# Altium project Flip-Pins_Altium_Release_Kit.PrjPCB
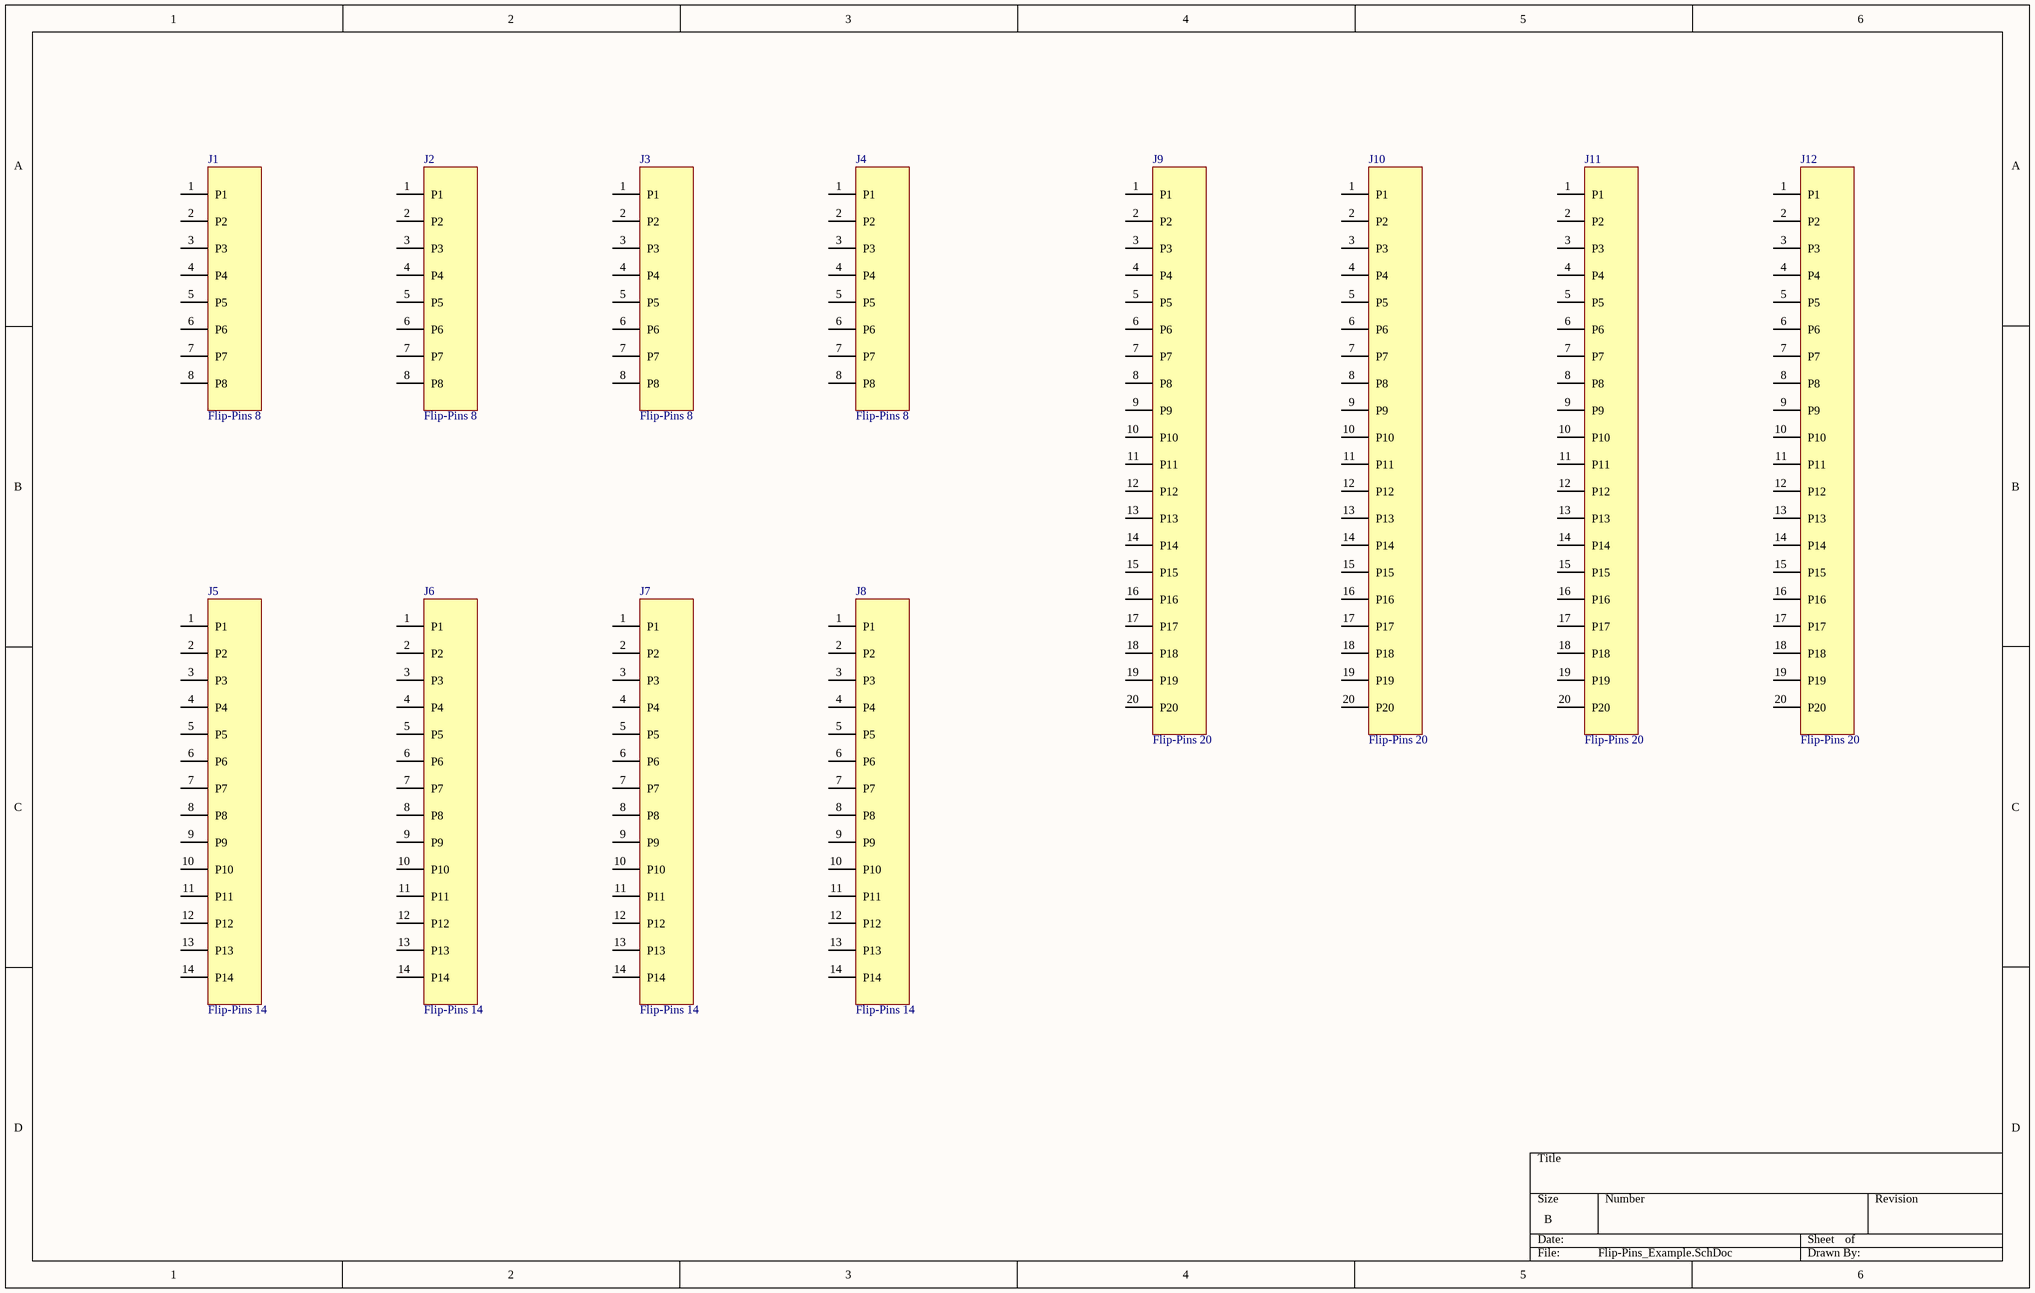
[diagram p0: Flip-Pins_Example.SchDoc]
1 sheet, 12 parts. Net scope: global (net labels, ports and power ports of the same name join across sheets).
Board file: Flip-Pins_Example.PcbDoc

## Sheet Flip-Pins_Example.SchDoc
size B

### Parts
J1  Flip-Pins 8  [Flip-Pins-08]
J2  Flip-Pins 8  [Flip-Pins-08]
J3  Flip-Pins 8  [Flip-Pins-08_Aligner]
J4  Flip-Pins 8  [Flip-Pins-08_Aligner]
J5  Flip-Pins 14  [Flip-Pins-14]
J6  Flip-Pins 14  [Flip-Pins-14]
J7  Flip-Pins 14  [Flip-Pins-14_Aligner]
J8  Flip-Pins 14  [Flip-Pins-14_Aligner]
J9  Flip-Pins 20  [Flip-Pins-20]
J10  Flip-Pins 20  [Flip-Pins-20]
J11  Flip-Pins 20  [Flip-Pins-20_Aligner]
J12  Flip-Pins 20  [Flip-Pins-20_Aligner]

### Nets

Not connected (* = marked no-connect by the designer): J1 1(P1) 2(P2) 3(P3) 4(P4) 5(P5) 6(P6) 7(P7) 8(P8); J2 1(P1) 2(P2) 3(P3) 4(P4) 5(P5) 6(P6) 7(P7) 8(P8); J3 1(P1) 2(P2) 3(P3) 4(P4) 5(P5) 6(P6) 7(P7) 8(P8); J4 1(P1) 2(P2) 3(P3) 4(P4) 5(P5) 6(P6) 7(P7) 8(P8); J5 1(P1) 2(P2) 3(P3) 4(P4) 5(P5) 6(P6) 7(P7) 8(P8) 9(P9) 10(P10) 11(P11) 12(P12) 13(P13) 14(P14); J6 1(P1) 2(P2) 3(P3) 4(P4) 5(P5) 6(P6) 7(P7) 8(P8) 9(P9) 10(P10) 11(P11) 12(P12) 13(P13) 14(P14); J7 1(P1) 2(P2) 3(P3) 4(P4) 5(P5) 6(P6) 7(P7) 8(P8) 9(P9) 10(P10) 11(P11) 12(P12) 13(P13) 14(P14); J8 1(P1) 2(P2) 3(P3) 4(P4) 5(P5) 6(P6) 7(P7) 8(P8) 9(P9) 10(P10) 11(P11) 12(P12) 13(P13) 14(P14); J9 1(P1) 2(P2) 3(P3) 4(P4) 5(P5) 6(P6) 7(P7) 8(P8) 9(P9) 10(P10) 11(P11) 12(P12) 13(P13) 14(P14) 15(P15) 16(P16) 17(P17) 18(P18) 19(P19) 20(P20); J10 1(P1) 2(P2) 3(P3) 4(P4) 5(P5) 6(P6) 7(P7) 8(P8) 9(P9) 10(P10) 11(P11) 12(P12) 13(P13) 14(P14) 15(P15) 16(P16) 17(P17) 18(P18) 19(P19) 20(P20); J11 1(P1) 2(P2) 3(P3) 4(P4) 5(P5) 6(P6) 7(P7) 8(P8) 9(P9) 10(P10) 11(P11) 12(P12) 13(P13) 14(P14) 15(P15) 16(P16) 17(P17) 18(P18) 19(P19) 20(P20); J12 1(P1) 2(P2) 3(P3) 4(P4) 5(P5) 6(P6) 7(P7) 8(P8) 9(P9) 10(P10) 11(P11) 12(P12) 13(P13) 14(P14) 15(P15) 16(P16) 17(P17) 18(P18) 19(P19) 20(P20)

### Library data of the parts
J1-J4 = J Flip-Pins-08
J5-J8 = J Flip-Pins-14
J9-J12 = J Flip-Pins-20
